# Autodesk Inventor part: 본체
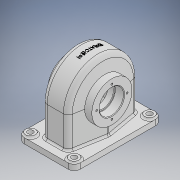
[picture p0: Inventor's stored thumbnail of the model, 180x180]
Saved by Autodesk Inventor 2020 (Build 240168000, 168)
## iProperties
Created: 2025-05
Part Number: 본체
Material: 일반
Document SubType Name: Modeling
Designer: CA01
Density: 1 g/cm^3
Appearance: 기본값
Author: CA01
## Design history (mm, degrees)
sketch "스케치2"
  geometry: L1 (30.051, 0)-(-30.051, 0); L2 (-30.051, 0)-(-20, 57); L3 (-20, 57)-(20, 57); L4 (20, 57)-(30.051, 0); L5 (0, -3231.553)-(0, 3231.553) reference; L6 (-30.051, 0)-(-20, -57); L7 (-20, -57)-(20, -57); L8 (20, -57)-(30.051, 0); L9 (0, 3231.553)-(0, -3231.553); L10 (12, 0)-(-12, 0); L11 (-12, 0)-(-12, 24); L12 (-12, 24)-(12, 24); L13 (12, 24)-(12, 0); L14 (12, -24)-(12, 0); L15 (-12, -24)-(12, -24); L16 (-12, 0)-(-12, -24); L17 (-25.127, -0.868)-(-15.805, 52); L18 (-15.805, 52)-(15.805, 52); L19 (15.805, 52)-(25.127, -0.868); L20 (-25.127, 0.868)-(-15.805, -52); L21 (-15.805, -52)-(15.805, -52); L22 (15.805, -52)-(25.127, 0.868); L23 (20.742, 24)-(-20.742, 24); 8 further points
  constraints: 44 end point, 6 symmetric about line, 3 horizontal, 3 midpoint, 3 parallel, 3 point on line, 2 coincident, 1 perpendicular, 6 other
  dimensions: "d4" = 57 distance between parallel lines of L1 L3; "d6" = 20 deg angle of L4 L2; "d7" = 40 distance of L2.end L3.end; "d67" = 24 distance of L11.end L12.end; "d68" = 24 distance of L12.end L10.start; "d69" = 5 distance between parallel lines of L2 L17; "d70" = 5 distance between parallel lines of L6 L20
revolve "회전1" stored, may be unused: angle "d8" = 90 deg
extrude "돌출1" join sketch "스케치2" distance "d9" = 60; taper "d10" = 0 deg
sketch "스케치3"
  geometry: L1 (46, 72)-(-46, 72); L2 (-46, 72)-(-46, -72); L3 (-46, -72)-(46, -72); L4 (46, -72)-(46, 72); 3 further points
  constraints: 8 end point, 2 midpoint, 2 parallel, 1 horizontal, 1 horizontal alignment, 1 perpendicular, 1 vertical alignment
  dimensions: "d11" = 92 distance of L1.start L1.end; "d12" = 144 distance of L3.end L1.start
extrude "돌출2" join sketch "스케치3" distance "d13" = 9; taper "d14" = 0 deg
fillet "모깎기1" dims "d15" = 10
fillet "모깎기2" dims "d16" = 8
node "작업 평면1"
node "작업 평면2"
sketch "스케치4"
  geometry: C1 r 33 at (0, 0); A1 r 57 centre (0, 0) between (0, -57) and (0, 57) reference; 1 further point
  constraints: 2 coincident, 1 centre point
  dimensions: "d24" = 66 diameter of C1
extrude "돌출3" join sketch "스케치4" stored distance "d25" = 9; taper "d26" = 0 deg
sketch "스케치5"
  geometry: C1 r 33 at (0, 0); A1 r 57 centre (0, 0) between (0, -57) and (0, 57) reference; 1 further point
  constraints: 1 centre point, 1 coincident
  dimensions: "d27" = 66 diameter of C1
extrude "돌출4" join sketch "스케치5" stored distance "d28" = 9; taper "d29" = 0 deg
sketch "스케치6"
  geometry: L1 (36, 33)-(36, -33) reference; L2 (36, -20)-(21.6, -20); L3 (21, -19.4)-(21, -17.5); L4 (21, -17.5)-(-21, -17.5); L5 (-21, -17.5)-(-21, -19.4); L6 (-21.6, -20)-(-36, -20); L7 (-36, -20)-(-36, 0); L8 (-36, 33)-(-36, -33) reference; L9 (36, -20)-(36, 0); L10 (-36, 0)-(36, 0); A1 r 0.6 centre (21.6, -19.4) between (21, -19.4) and (21.6, -20); A2 r 0.6 centre (-21.6, -19.4) between (-21.6, -20) and (-21, -19.4); 3 further points
  constraints: 16 end point, 5 point on line, 4 perpendicular, 4 point on circle, 4 tangent, 2 centre point, 2 midpoint, 2 vertical, 1 equal radius, 1 horizontal
  dimensions: "d31" = 40 diameter of L2 L10; "d32" = 35 diameter of L4 L10; "d33" = 40 diameter of L6 L10; "d34" = 15 distance of point (-21, -20) L6.end; "d35" = 15 distance of L2.start point (21, -20); "d37" = 0.6 radius of A1
revolve "회전2" sketch "스케치6" stored, may be unused: angle "d38" = 90 deg
chamfer "모따기1" distance "d39" = 1; stored, may be unused: second distance "d40" = 2, angle "d41" = 45 deg
sketch "스케치8"
  geometry: 2 further points
  constraints: 2 coincident, 1 other
feature "엠보싱1" sketch "스케치8" dims "d4" = 57, "d6" = 20 deg, "d7" = 40, "d15" = 10, "d43" = 0.5, "d44" = 0, "d67" = 24, "d68" = 24, "d69" = 5, "d70" = 5
sketch "스케치9" dims "d52" = 50
  geometry: L1 (0, 0)-(0, 25); 2 further points
  constraints: 2 coincident, 2 end point, 1 vertical, 1 vertical alignment, 2 other
hole "구멍1" sketch "스케치9" at (0, 25) diameter "d45" = 3.242; stored, may be unused: countersink angle "d49" = 90 deg, drill point angle "d51" = 118 deg; dims "d46" = 8, "d47" = 4, "d48" = 2, "d50" = 10
sketch "스케치10"
  geometry: L1 (0, 0)-(0, 25); C1 r 25 at (0, 0); C2 r 1.621 at (0, 25) reference; 2 further points
  constraints: 2 coincident, 2 end point, 1 centre point, 1 vertical
  dimensions: "d63" = 50 diameter of C1
hole "구멍2" sketch "스케치10" at (0, 25) diameter "d56" = 3.242; stored, may be unused: countersink angle "d60" = 90 deg, drill point angle "d62" = 118 deg; dims "d57" = 8, "d58" = 4, "d59" = 2, "d61" = 10
sketch "스케치11"
  geometry: 1 further point
sketch "스케치12"
  geometry: 1 further point
sketch "스케치13" dims "d4" = 57, "d6" = 20 deg, "d7" = 40, "d67" = 24, "d68" = 24, "d69" = 5, "d70" = 5
  geometry: L1 (-21.166, -50.389)-(-29.806, -1.389) reference; L2 (13.287, -57)-(-13.287, -57) reference; L3 (29.806, -1.389)-(21.166, -50.389) reference; L4 (21.166, 50.389)-(29.806, 1.389) reference; L5 (-13.287, 57)-(13.287, 57) reference; L6 (-29.806, 1.389)-(-21.166, 50.389) reference; L7 (-24.882, -0.521)-(-16.242, -49.521); L8 (-13.287, -52)-(13.287, -52); L9 (16.242, -49.521)-(24.882, -0.521); L10 (24.882, 0.521)-(16.242, 49.521); L11 (13.287, 52)-(-13.287, 52); L12 (-16.242, 49.521)-(-24.882, 0.521); A1 r 8 centre (-13.287, -49) between (-21.166, -50.389) and (-13.287, -57) reference; A2 r 8 centre (13.287, -49) between (13.287, -57) and (21.166, -50.389) reference; A3 r 8 centre (21.927, 0) between (29.806, -1.389) and (29.806, 1.389) reference; A4 r 8 centre (13.287, 49) between (21.166, 50.389) and (13.287, 57) reference; A5 r 8 centre (-13.287, 49) between (-13.287, 57) and (-21.166, 50.389) reference; A6 r 8 centre (-21.927, 0) between (-29.806, 1.389) and (-29.806, -1.389) reference; A7 r 3 centre (-13.287, -49) between (-16.242, -49.521) and (-13.287, -52); A8 r 3 centre (13.287, -49) between (13.287, -52) and (16.242, -49.521); A9 r 3 centre (21.927, 0) between (24.882, -0.521) and (24.882, 0.521); A10 r 3 centre (13.287, 49) between (16.242, 49.521) and (13.287, 52); A11 r 3 centre (-13.287, 49) between (-13.287, 52) and (-16.242, 49.521); A12 r 3 centre (-21.927, 0) between (-24.882, 0.521) and (-24.882, -0.521); 1 further point
  constraints: 12 end point, 12 point on circle, 6 centre point, 11 other
  dimensions: "d71" = 5 distance between parallel lines of L1 L7
extrude "돌출5" cut sketch "스케치13" distance "d72" = 36; taper "d73" = 0 deg
sketch "스케치14"
  geometry: L1 (-46, 62)-(-46, -62) reference; L2 (-36, -72)-(36, -72) reference; L3 (46, -62)-(46, 62) reference; L4 (36, 72)-(-36, 72) reference; L5 (-21.166, 50.389)-(-29.806, 1.389) reference; L6 (13.287, 57)-(-13.287, 57) reference; L7 (29.806, 1.389)-(21.166, 50.389) reference; L8 (21.166, -50.389)-(29.806, -1.389) reference; L9 (-13.287, -57)-(13.287, -57) reference; L10 (-29.806, -1.389)-(-21.166, -50.389) reference; C1 r 8 at (36, 62); C2 r 8 at (36, -62); C3 r 8 at (-36, -62); C4 r 8 at (-36, 62); A1 r 10 centre (-36, 62) between (-36, 72) and (-46, 62) reference; A2 r 10 centre (-36, -62) between (-46, -62) and (-36, -72) reference; A3 r 10 centre (36, -62) between (36, -72) and (46, -62) reference; A4 r 10 centre (36, 62) between (46, 62) and (36, 72) reference; A5 r 8 centre (-13.287, 49) between (-13.287, 57) and (-21.166, 50.389) reference; A6 r 8 centre (13.287, 49) between (21.166, 50.389) and (13.287, 57) reference; A7 r 8 centre (21.927, 0) between (29.806, -1.389) and (29.806, 1.389) reference; A8 r 8 centre (13.287, -49) between (13.287, -57) and (21.166, -50.389) reference; A9 r 8 centre (-13.287, -49) between (-21.166, -50.389) and (-13.287, -57) reference; A10 r 8 centre (-21.927, 0) between (-29.806, 1.389) and (-29.806, -1.389) reference; 1 further point
  constraints: 4 centre point, 4 coincident
  dimensions: "d74" = 16 diameter of C1; "d75" = 16 diameter of C2; "d76" = 16 diameter of C3; "d77" = 16 diameter of C4
extrude "돌출6" join sketch "스케치14" distance "d78" = 3; taper "d79" = 0 deg
sketch "스케치15"
  geometry: C1 r 8 at (0, 0) reference; C2 r 4.5 at (0, 0); C3 r 8 at (72, 0) reference; C4 r 8 at (72, -124) reference; C5 r 8 at (0, -124) reference; C6 r 4.5 at (72, 0); C7 r 4.5 at (72, -124); C8 r 4.5 at (0, -124); 1 further point
  constraints: 4 centre point, 4 coincident
  dimensions: "d81" = 9 diameter of C2; "d84" = 9 diameter of C6; "d85" = 9 diameter of C7; "d86" = 9 diameter of C8
extrude "돌출7" cut sketch "스케치15" distance "d82" = 12; taper "d83" = 0 deg
fillet "모깎기5" dims "d87" = 3
sketch "스케치16"
  geometry: L1 (12, 24)-(-12, 24); L2 (-12, 24)-(-12, -24); L3 (-12, -24)-(12, -24); L4 (12, -24)-(12, 24); L5 (13.287, 0)-(13.287, -51) reference; L6 (13.287, 0)-(-13.287, 0) reference; L7 (13.287, 0)-(-13.287, 0); 4 further points
  constraints: 10 end point, 2 parallel, 2 perpendicular, 1 horizontal, 1 midpoint, 1 vertical alignment
  dimensions: "d88" = 24 distance of L1.start L1.end; "d89" = 24 distance from line of point (0, 0) L1; "d90" = 24 distance from line of L3 point (0, 0)
revolve "회전3" sketch "스케치16" stored, may be unused: angle "d91" = 90 deg
fillet "모깎기6" dims "d92" = 3
sketch "스케치17"
  geometry: 1 further point
node "솔리드1"
pattern_circular "원형 패턴1" dims angle "d54" = 360 deg
pattern_circular "원형 패턴2" dims angle "d65" = 360 deg
node "투영된 루프1"
node "투영된 루프2"
node "투영된 루프3"
node "투영된 루프4"
node "투영된 루프5"
feature "A9D066F2-1C7D-4E18-AEED-F7BC21143FA4" dims "d45" = 3.242, "d46" = 8, "d47" = 4, "d48" = 2, "d49" = 90 deg, "d50" = 10, "d51" = 118 deg
other parameters: "d22" = 36, "d23" = -36
